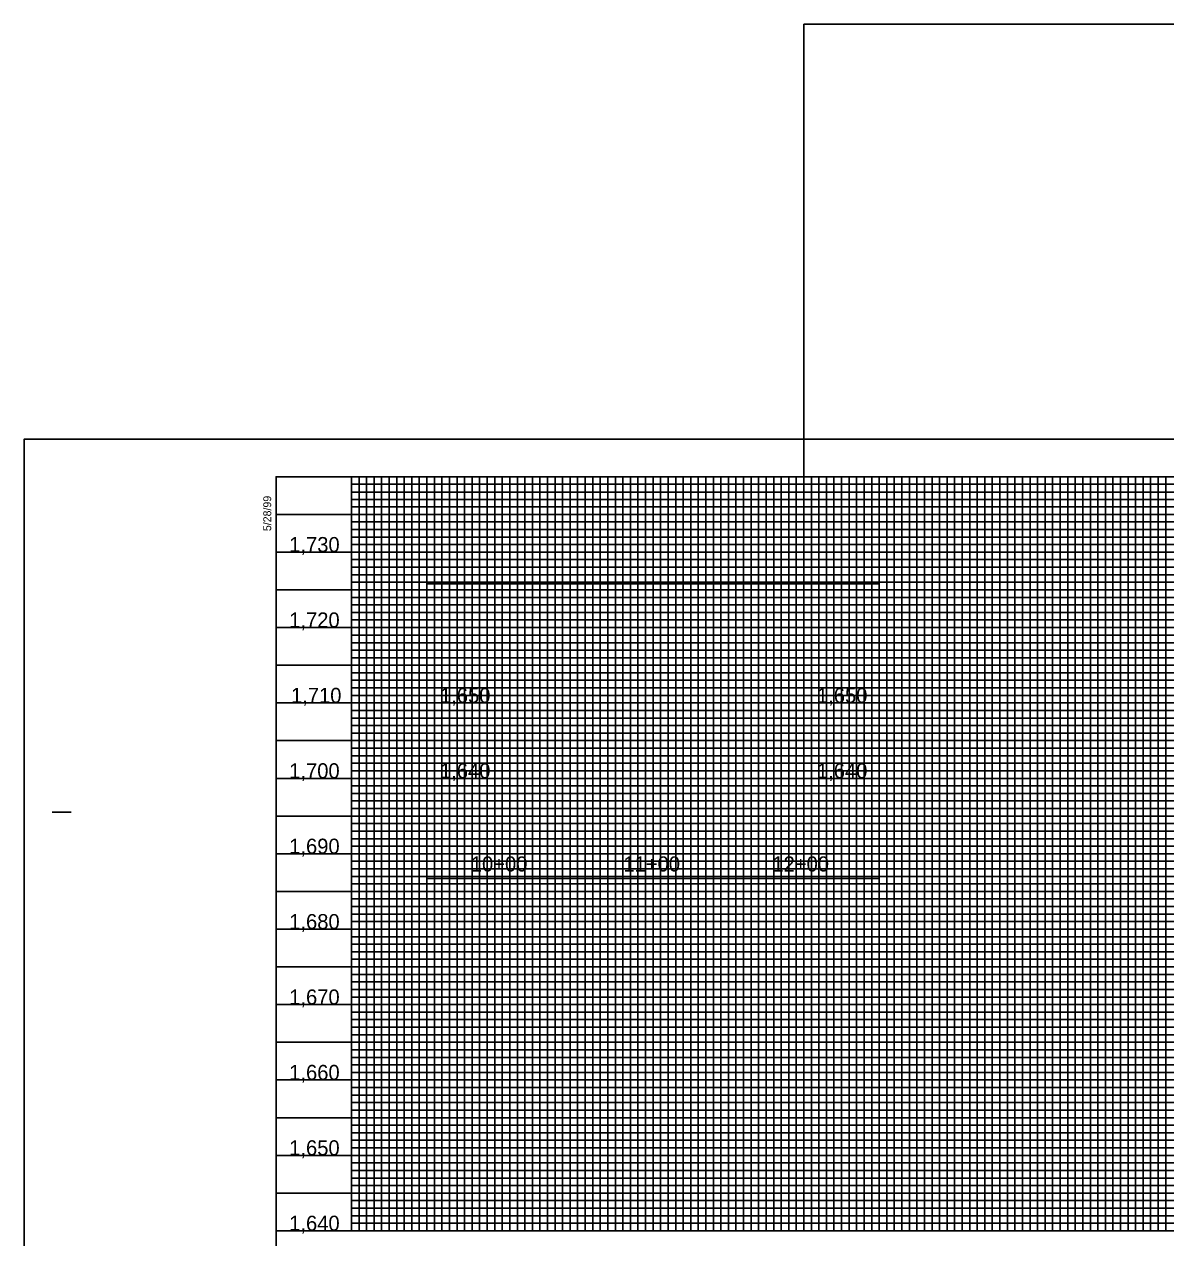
# Model space of a CAD drawing. Extents: x 505569 to 516904, y 436011 to 484484.
# Drawn here: x 505602 to 506359, y 483679 to 484484 of the extents above; entities that cross this region are included whole.
import ezdxf

# ---------------------------------------------------------------- set-up
doc = ezdxf.new("R2010")
doc.units = 0
for name, color, linetype in [('COGO Default Curve', 7, 'Continuous'), ('Exist Profile Cell', 7, 'Continuous'), ('Exist Vertical Profile Ground Line', 7, 'Continuous'), ('Exist Vertical Profile Vertical Axis Label', 7, 'Continuous'), ('Prop Grid Mask', 7, 'Continuous'), ('Prop Vertical Profile Curve Label', 7, 'Continuous'), ('Prop Vertical Profile Grade Label', 7, 'Continuous'), ('Scratch_Level_2', 7, 'Continuous'), ('Scratch_Level_8', 7, 'Continuous')]:
    doc.layers.add(name, color=color, linetype=linetype)

msp = doc.modelspace()

# ---------------------------------------------------------------- linework, layer by layer
at = {"layer": 'COGO Default Curve'}
msp.add_line((505769.08, 484158.71), (507069.03, 484158.71), dxfattribs=at)
msp.add_line((505769.08, 484158.71), (507069.03, 484158.71), dxfattribs=at)
for points in [[(505844.08, 484183.71), (505844.08, 483683.71), (505894.08, 483683.71), (505894.08, 484183.71), (505944.08, 484183.71), (505944.08, 483683.71), (505994.08, 483683.71), (505994.08, 484183.71), (506044.08, 484183.71), (506044.08, 483683.71), (506094.08, 483683.71), (506094.08, 484183.71), (506144.08, 484183.71), (506144.08, 483683.71), (506194.08, 483683.71), (506194.08, 484183.71), (506244.08, 484183.71), (506244.08, 483683.71), (506294.08, 483683.71), (506294.08, 484183.71), (506344.08, 484183.71), (506344.08, 483683.71), (506394.08, 483683.71)], [(507069.08, 484108.71), (505769.08, 484108.71), (505769.08, 484058.71), (507069.08, 484058.71)], [(507269.08, 484008.71), (505769.08, 484008.71), (505769.08, 483958.71), (507094.08, 483958.71)], [(507269.08, 483908.71), (505769.08, 483908.71), (505769.08, 483858.71), (507269.08, 483858.71)], [(507269.08, 483808.71), (505769.08, 483808.71), (505769.08, 483758.71), (507269.08, 483758.71)], [(507269.08, 483708.71), (505769.08, 483708.71)]]:
    msp.add_lwpolyline(points, dxfattribs=at)
at = {"layer": 'Exist Vertical Profile Ground Line'}
msp.add_lwpolyline([(505869.08, 483933.71), (506169.08, 483933.71), (506169.08, 483917.26), (505869.08, 483917.26)], close=True, dxfattribs=at)
at = {"layer": 'Exist Vertical Profile Vertical Axis Label'}
for points in [[(506119.08, 484483.71), (507319.08, 484483.71), (507319.08, 483983.71), (507319.08, 483983.71), (507319.08, 483983.71), (506119.08, 483983.71)], [(505819.08, 484183.71), (505819.08, 483683.71), (507019.08, 483683.71), (507019.08, 483998.71), (507019.08, 484053.71), (507019.08, 484183.71)], [(505819.08, 484183.71), (507019.08, 484183.71), (507019.08, 483683.71), (507019.08, 483683.71), (507019.08, 483683.71), (505819.08, 483683.71)]]:
    msp.add_lwpolyline(points, close=True, dxfattribs=at)
at = {"layer": 'Prop Grid Mask'}
msp.add_lwpolyline([(505602.08, 483108.71), (507286.08, 483108.71), (507286.08, 484208.71), (505602.08, 484208.71)], close=True, dxfattribs=at)
at = {"layer": 'Prop Vertical Profile Curve Label'}
for p, q in [((505869.08, 483917.26), (505869.08, 484112.66)), ((505869.08, 484112.66), (506169.08, 484112.66)), ((505919.08, 483933.71), (505919.08, 484112.66)), ((506119.08, 483933.71), (506119.08, 484112.66)), ((506169.08, 483917.26), (506169.08, 484112.66)), ((505620.58, 483961.21), (505633.08, 483961.21)), ((505869.08, 483933.71), (506169.08, 483933.71)), ((505869.08, 483917.26), (506169.08, 483917.26)), ((505769.08, 483683.71), (507269.08, 483683.71))]:
    msp.add_line(p, q, dxfattribs=at)
msp.add_lwpolyline([(507269.08, 484183.71), (505769.08, 484183.71), (505769.08, 483133.71), (507269.08, 483133.71)], close=True, dxfattribs=at)
at = {"layer": 'Prop Vertical Profile Grade Label'}
for p, q in [((505819.08, 484178.71), (507069.08, 484178.71)), ((505819.08, 484173.71), (505819.08, 484173.71)), ((507069.08, 484173.71), (505819.08, 484173.36)), ((505819.08, 484168.71), (507069.08, 484168.71)), ((507069.03, 484048.71), (505819.08, 484048.71)), ((507069.08, 484043.71), (505819.08, 484043.71)), ((507069.08, 484038.71), (505819.08, 484038.71)), ((505819.08, 484028.71), (507069.08, 484028.71)), ((507069.08, 484023.71), (505819.08, 484023.71)), ((505819.08, 484018.71), (507219.08, 484018.71)), ((507219.08, 483998.71), (505819.08, 483998.71)), ((505819.08, 483993.71), (507219.08, 483993.71)), ((507219.08, 483973.71), (505819.08, 483973.71)), ((505819.08, 483968.71), (507219.08, 483968.71)), ((507219.08, 483948.71), (505819.08, 483948.71)), ((505819.08, 483943.71), (507219.08, 483943.71)), ((507219.08, 483938.71), (505819.08, 483938.71)), ((505819.08, 483928.71), (507219.08, 483928.71)), ((507219.08, 483923.71), (505819.08, 483923.71)), ((505819.08, 483918.71), (507219.08, 483918.71)), ((507219.08, 483913.71), (505819.08, 483913.71)), ((505819.08, 483903.71), (507219.08, 483903.71)), ((507219.08, 483898.71), (505819.08, 483898.71)), ((505819.08, 483893.71), (507219.08, 483893.71)), ((507219.08, 483888.71), (505819.08, 483888.71)), ((505819.08, 483878.71), (507219.08, 483878.71)), ((507219.08, 483873.71), (505819.08, 483873.71)), ((505819.08, 483868.71), (507219.08, 483868.71)), ((507219.08, 483863.71), (505819.08, 483863.71)), ((505819.08, 483853.71), (507219.08, 483853.71)), ((507219.08, 483848.71), (505819.08, 483848.71)), ((505819.08, 483843.71), (507219.08, 483843.71)), ((507219.08, 483838.71), (505819.08, 483838.71)), ((505819.08, 483828.71), (507219.08, 483828.71)), ((507219.08, 483823.71), (505819.08, 483823.71)), ((505819.08, 483818.71), (507219.08, 483818.71)), ((507219.08, 483813.71), (505819.08, 483813.71)), ((505819.08, 483803.71), (507219.08, 483803.71)), ((507219.08, 483798.71), (505819.08, 483798.71)), ((507219.08, 483793.71), (505819.08, 483793.71)), ((507219.08, 483788.71), (505819.08, 483788.71)), ((505819.08, 483778.71), (507219.08, 483778.71)), ((507219.08, 483773.71), (505819.08, 483773.71)), ((505819.08, 483768.71), (507219.08, 483768.71)), ((507219.08, 483763.71), (505819.08, 483763.71)), ((505819.08, 483753.71), (507219.08, 483753.71)), ((507219.08, 483748.71), (505819.08, 483748.71)), ((505819.08, 483743.71), (507219.08, 483743.71)), ((507219.08, 483738.71), (505819.08, 483738.71)), ((505819.08, 483728.71), (507219.08, 483728.71)), ((507219.08, 483723.71), (505819.08, 483723.71)), ((505819.08, 483718.71), (507219.08, 483718.71)), ((507219.08, 483713.71), (505819.08, 483713.71)), ((505819.08, 483703.71), (507219.08, 483703.71)), ((507219.08, 483698.71), (505819.08, 483698.71)), ((505819.08, 483693.71), (507219.08, 483693.71))]:
    msp.add_line(p, q, dxfattribs=at)
for points in [[(505824.08, 484183.71), (505824.08, 483683.71), (505829.08, 483683.71), (505829.08, 484183.71), (505834.08, 484183.71), (505834.08, 483683.71), (505839.08, 483683.71), (505839.08, 484183.71), (505849.08, 484183.71), (505849.08, 483683.71), (505854.08, 483683.71), (505854.08, 484183.71), (505859.08, 484183.71), (505859.08, 483683.71), (505864.08, 483683.71), (505874.08, 483683.71), (505879.08, 483683.71), (505879.08, 484183.71), (505884.08, 484183.71), (505884.08, 483683.71), (505889.08, 483683.71), (505889.08, 484183.71), (505899.08, 484183.71), (505899.08, 483683.71), (505904.08, 483683.71), (505904.08, 484183.71), (505909.08, 484183.71), (505909.08, 483683.71), (505914.08, 483683.71), (505914.08, 484183.71), (505924.08, 484183.71), (505924.08, 483683.71), (505929.08, 483683.71), (505929.08, 484183.71), (505934.08, 484183.71), (505934.08, 483683.71), (505939.08, 483683.71), (505939.08, 484183.71), (505949.08, 484183.71), (505949.08, 483683.71), (505954.08, 483683.71), (505954.08, 484183.71), (505959.08, 484183.71), (505959.08, 483683.71), (505964.08, 483683.71), (505964.08, 484183.71), (505974.08, 484183.71), (505974.08, 483683.71), (505979.08, 483683.71), (505979.08, 484183.71), (505984.08, 484183.71), (505984.08, 483683.71), (505989.08, 483683.71), (505989.08, 484183.71), (505999.08, 484183.71), (505999.08, 483683.71), (506004.08, 483683.71), (506004.08, 484183.71), (506009.08, 484183.71), (506009.08, 483683.71), (506014.08, 483683.71), (506014.08, 484183.71), (506024.08, 484183.71), (506024.08, 483683.71), (506029.08, 483683.71), (506029.08, 484183.71), (506034.08, 484183.71), (506034.08, 483683.71)], [(505864.08, 483683.71), (505864.08, 484183.71), (505874.08, 484183.71), (505874.08, 483683.71)], [(506034.08, 483683.71), (506039.08, 483683.71), (506039.08, 484183.71), (506049.08, 484183.71), (506049.08, 483683.71), (506054.08, 483683.71), (506054.08, 484183.71), (506059.08, 484183.71), (506059.08, 483683.71), (506064.08, 483683.71), (506064.08, 484183.71), (506074.08, 484183.71), (506074.08, 483683.71), (506079.08, 483683.71), (506079.08, 484183.71), (506084.08, 484183.71), (506084.08, 483683.71), (506089.08, 483683.71), (506089.08, 484183.71), (506099.08, 484183.71), (506099.08, 483683.71), (506104.08, 483683.71), (506104.08, 484183.71), (506109.08, 484183.71), (506109.08, 483683.71), (506114.08, 483683.71), (506114.08, 484183.71), (506124.08, 484183.71), (506124.08, 483683.71), (506129.08, 483683.71), (506129.08, 484183.71), (506134.08, 484183.71), (506134.08, 483683.71), (506139.08, 483683.71), (506139.08, 484183.71), (506149.08, 484183.71), (506149.08, 483683.71), (506154.08, 483683.71), (506154.08, 484183.71), (506159.08, 484183.71), (506159.08, 483683.71), (506164.08, 483683.71), (506164.08, 484183.71), (506174.08, 484183.71), (506174.08, 483683.71), (506179.08, 483683.71), (506179.08, 484183.71), (506184.08, 484183.71), (506184.08, 483683.71), (506189.08, 483683.71), (506189.08, 484183.71), (506199.08, 484183.71), (506199.08, 483683.71), (506204.08, 483683.71), (506204.08, 484183.71), (506209.08, 484183.71), (506209.08, 483683.71), (506214.08, 483683.71), (506214.08, 484183.71), (506224.08, 484183.71), (506224.08, 483683.71), (506229.08, 483683.71), (506229.08, 484183.71), (506234.08, 484183.71), (506234.08, 483683.71), (506239.08, 483683.71), (506239.08, 484183.71), (506249.08, 484183.71), (506249.08, 483683.71), (506254.08, 483683.71), (506254.08, 484183.71), (506259.08, 484183.71), (506259.08, 483683.71), (506264.08, 483683.71), (506264.08, 484183.71), (506274.08, 484183.71), (506274.08, 483683.71), (506279.08, 483683.71), (506279.08, 484183.71), (506284.08, 484183.71), (506284.08, 483683.71), (506289.08, 483683.71), (506289.08, 484183.71), (506299.08, 484183.71), (506299.08, 483683.71), (506304.08, 483683.71), (506304.08, 484183.71), (506309.08, 484183.71), (506309.08, 483683.71), (506314.08, 483683.71), (506314.08, 484183.71), (506324.08, 484183.71), (506324.08, 483683.71), (506329.08, 483683.71), (506329.08, 484183.71), (506334.08, 484183.71), (506334.08, 483683.71), (506339.08, 483683.71), (506339.08, 484183.71), (506349.08, 484183.71)], [(506349.08, 484183.71), (506349.08, 483683.71), (506354.08, 483683.71), (506354.08, 484183.71), (506359.08, 484183.71), (506359.08, 483683.71), (506364.08, 483683.71)], [(507069.08, 484163.71), (505819.08, 484163.71), (505819.08, 484153.71), (507069.08, 484153.71)], [(507069.03, 484148.71), (505819.08, 484148.71), (505819.08, 484143.71), (507069.08, 484143.71)], [(507069.08, 484138.71), (505819.08, 484138.71), (505819.08, 484128.71), (507069.08, 484128.71)], [(507069.08, 484123.71), (505819.08, 484123.71), (505819.08, 484118.71), (507069.08, 484118.71)], [(507069.08, 484113.71), (505819.08, 484113.71), (505819.08, 484103.71), (507069.08, 484103.71)], [(507069.08, 484098.71), (505819.08, 484098.71), (505819.08, 484093.71), (507069.08, 484093.71)], [(507069.08, 484088.71), (505819.08, 484088.71), (505819.08, 484078.71), (507069.08, 484078.71)], [(507069.08, 484073.61), (505819.18, 484073.61), (505819.18, 484068.71), (507069.08, 484068.71)], [(507069.08, 484063.71), (505819.08, 484063.71), (505819.08, 484053.71), (507069.08, 484053.71)], [(507219.08, 484013.71), (505819.08, 484013.71), (505819.08, 484003.71), (507219.08, 484003.71)], [(507219.08, 483988.71), (505819.08, 483988.71), (505819.08, 483978.71), (507219.08, 483978.71)], [(507219.08, 483963.71), (505819.08, 483963.71), (505819.08, 483953.71), (507219.08, 483953.71)], [(507219.08, 483688.71), (505819.08, 483688.71)]]:
    msp.add_lwpolyline(points, dxfattribs=at)
at = {"layer": 'Scratch_Level_2'}
for points in [[(505819.08, 484183.71), (505819.08, 483683.71), (505869.08, 483683.71), (505869.08, 484183.71), (505919.08, 484183.71), (505919.08, 483683.71), (505969.08, 483683.71), (505969.08, 484183.71), (506019.08, 484183.71), (506019.08, 483683.71), (506069.08, 483683.71), (506069.08, 484183.71), (506119.08, 484183.71), (506119.08, 483683.71), (506169.08, 483683.71), (506169.08, 484183.71), (506219.08, 484183.71), (506219.08, 483683.71), (506269.08, 483683.71), (506269.08, 484183.71), (506319.08, 484183.71), (506319.08, 483683.71), (506369.08, 483683.71)], [(505769.08, 484133.71), (507069.08, 484133.71)], [(507069.08, 484083.71), (505769.08, 484083.71), (505769.08, 484033.71), (507069.08, 484033.71)], [(507269.08, 483983.71), (505769.08, 483983.71), (505769.08, 483933.71), (507269.08, 483933.71)], [(507269.08, 483883.71), (505769.08, 483883.71), (505769.08, 483833.71), (507269.08, 483833.71)], [(507269.08, 483783.71), (505769.08, 483783.71), (505769.08, 483783.71), (505769.08, 483733.71), (507269.08, 483733.71)]]:
    msp.add_lwpolyline(points, dxfattribs=at)
at = {"layer": 'Scratch_Level_8'}
for points in [[(505919.08, 484112.66), (506119.08, 484112.66), (506119.08, 483933.71), (505919.08, 483933.71)], [(506119.08, 484112.66), (505919.08, 484112.66), (505919.08, 483933.71), (506119.08, 483933.71)]]:
    msp.add_lwpolyline(points, close=True, dxfattribs=at)

# ---------------------------------------------------------------- texts
at = {"layer": 'Exist Profile Cell'}
for s, p in [('1,730', (505777.78, 484133.71)), ('1,720', (505777.78, 484083.71)), ('1,710', (505778.97, 484033.71)), ('1,650', (505877.78, 484033.71)), ('1,650', (506127.78, 484033.71)), ('1,700', (505777.78, 483983.71)), ('1,640', (505877.78, 483983.71)), ('1,640', (506127.78, 483983.71)), ('1,690', (505777.78, 483933.71)), ('10+00', (505898.21, 483921.94)), ('11+00', (505999.41, 483921.94)), ('12+00', (506098.21, 483921.94)), ('1,680', (505777.78, 483883.71)), ('1,670', (505777.78, 483833.71)), ('1,660', (505777.78, 483783.71)), ('1,650', (505777.78, 483733.71)), ('1,640', (505777.78, 483683.71))]:
    msp.add_text(s, height=10, dxfattribs=at).set_placement(p)
at = {"layer": 'Prop Vertical Profile Curve Label'}
msp.add_text('5/28/99', height=5.25, rotation=90, dxfattribs=at).set_placement((505765.84, 484147.62))

doc.saveas('drawing.dxf')
